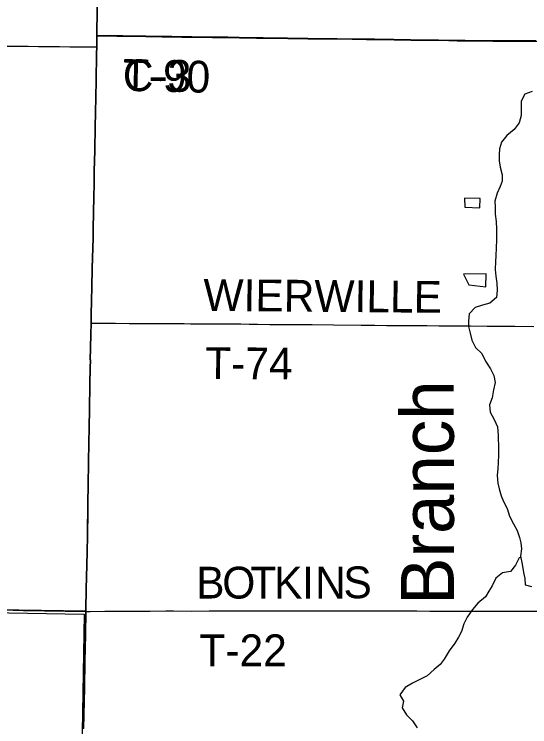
# Model space of a CAD drawing. Extents: x -11.1 to 34, y -3.9 to 22.
# Drawn here: x 7.271 to 8.192, y 18.032 to 19.305 of the extents above; entities that cross this region are included whole.
import ezdxf

# ---------------------------------------------------------------- set-up
doc = ezdxf.new("R2010")
doc.units = 0
for name, color, linetype in [('GM_X_Corporation', 7, 'Continuous'), ('GM_X_County_Road', 7, 'Continuous'), ('GM_X_County_Road_Text', 7, 'Continuous'), ('GM_X_Minor_Lake', 7, 'Continuous'), ('GM_X_Minor_River', 7, 'Continuous'), ('GM_X_Minor_River_Text', 7, 'Continuous'), ('GM_X_Township_Road', 7, 'Continuous'), ('GM_X_Township_Road_Text', 7, 'Continuous')]:
    doc.layers.add(name, color=color, linetype=linetype)

msp = doc.modelspace()

# ---------------------------------------------------------------- linework, layer by layer
at = {"layer": 'GM_X_Corporation'}
for points in [[(6.5234, 18.2515), (7.399, 18.2383), (7.399, 18.2404), (7.3996, 18.2783), (7.4004, 18.3205), (7.4009, 18.3448), (7.4015, 18.3721), (7.4021, 18.4162), (7.4025, 18.4348), (7.403, 18.4609), (7.4037, 18.5063), (7.4048, 18.5684), (7.4054, 18.5976), (7.4062, 18.6448), (7.4067, 18.6728), (7.4068, 18.6865), (7.4065, 18.6884), (7.4065, 18.6901), (7.4065, 18.695), (7.407, 18.7007), (7.4072, 18.7099), (7.4077, 18.7323), (7.4081, 18.7533), (7.4084, 18.7677), (7.4091, 18.7932), (7.4095, 18.8174), (7.4103, 18.851), (7.4116, 18.9056), (7.4119, 18.928), (7.4122, 18.9442), (7.4125, 18.9572), (7.4129, 18.9721), (7.4134, 19.0081), (7.4137, 19.0243), (7.4147, 19.0616), (7.4154, 19.1044), (7.4159, 19.1287), (7.4172, 19.1858), (7.418, 19.2337), (7.4182, 19.2471), (7.4185, 19.2665), (7.4229, 19.6584)], [(7.4229, 19.6584), (7.4185, 19.2665), (7.443, 19.2667), (7.4647, 19.2663), (7.5058, 19.2659), (7.5349, 19.2653), (7.5523, 19.2651), (7.5884, 19.2644), (7.625, 19.2641), (7.6524, 19.2639), (7.6729, 19.2635), (7.7158, 19.2629), (7.7593, 19.2623), (7.7953, 19.2619), (7.8481, 19.2613), (7.9146, 19.2604), (7.9494, 19.2599), (7.9792, 19.2594), (8.0289, 19.2587), (8.0768, 19.2579), (8.1153, 19.2577), (8.1258, 19.2576), (8.1476, 19.2574), (8.1693, 19.2576), (8.2029, 19.2576)], [(8.2029, 19.2576), (8.1693, 19.2576), (8.1476, 19.2574), (8.1258, 19.2576), (8.1153, 19.2577), (8.0768, 19.2579), (8.0289, 19.2587), (7.9792, 19.2594), (7.9494, 19.2599), (7.9146, 19.2604), (7.8481, 19.2613), (7.7953, 19.2619), (7.7593, 19.2623), (7.7158, 19.2629), (7.6729, 19.2635), (7.6524, 19.2639), (7.625, 19.2641), (7.5884, 19.2644), (7.5523, 19.2651), (7.5349, 19.2653), (7.5058, 19.2659), (7.4647, 19.2663), (7.443, 19.2667), (7.4185, 19.2665), (7.4182, 19.2471), (7.418, 19.2337), (7.4172, 19.1858), (7.4159, 19.1287), (7.4154, 19.1044), (7.4147, 19.0616), (7.4137, 19.0243), (7.4134, 19.0081), (7.4129, 18.9721), (7.4125, 18.9572), (7.4122, 18.9442), (7.4119, 18.928), (7.4116, 18.9056), (7.4103, 18.851), (7.4095, 18.8174), (7.4091, 18.7932), (7.4084, 18.7677), (7.4081, 18.7533), (7.4077, 18.7323), (7.4072, 18.7099), (7.407, 18.7007), (7.4065, 18.695), (7.4065, 18.6901), (7.4065, 18.6884), (7.4068, 18.6865), (7.4067, 18.6728), (7.4062, 18.6448), (7.4054, 18.5976), (7.4048, 18.5684), (7.4037, 18.5063), (7.403, 18.4609), (7.4025, 18.4348), (7.4021, 18.4162), (7.4015, 18.3721), (7.4009, 18.3448), (7.4004, 18.3205), (7.3996, 18.2783), (7.399, 18.2404), (7.399, 18.2383), (7.398, 18.1956), (7.3971, 18.149), (7.3961, 18.1012), (7.3946, 18.0285)], [(7.3946, 18.0285), (7.3961, 18.1012), (7.3971, 18.149), (7.398, 18.1956), (7.399, 18.2383), (7.399, 18.2404), (7.3996, 18.2783), (7.4004, 18.3205), (7.4009, 18.3448), (7.4015, 18.3721), (7.4021, 18.4162), (7.4025, 18.4348), (7.403, 18.4609), (7.4037, 18.5063), (7.4048, 18.5684), (7.4054, 18.5976), (7.4062, 18.6448), (7.4067, 18.6728), (7.4068, 18.6865), (7.4065, 18.6884), (7.4065, 18.6901), (7.4065, 18.695), (7.407, 18.7007), (7.4072, 18.7099), (7.4077, 18.7323), (7.4081, 18.7533), (7.4084, 18.7677), (7.4091, 18.7932), (7.4095, 18.8174), (7.4103, 18.851), (7.4116, 18.9056), (7.4119, 18.928), (7.4122, 18.9442), (7.4125, 18.9572), (7.4129, 18.9721), (7.4134, 19.0081), (7.4137, 19.0243), (7.4147, 19.0616), (7.4154, 19.1044), (7.4159, 19.1287), (7.4172, 19.1858), (7.418, 19.2337), (7.4182, 19.2471), (7.4185, 19.2665), (7.443, 19.2667), (7.4647, 19.2663), (7.5058, 19.2659), (7.5349, 19.2653), (7.5523, 19.2651), (7.5884, 19.2644), (7.625, 19.2641), (7.6524, 19.2639), (7.6729, 19.2635), (7.7158, 19.2629), (7.7593, 19.2623), (7.7953, 19.2619), (7.8481, 19.2613), (7.9146, 19.2604), (7.9494, 19.2599), (7.9792, 19.2594), (8.0289, 19.2587), (8.0768, 19.2579), (8.1153, 19.2577), (8.1258, 19.2576), (8.1476, 19.2574), (8.1693, 19.2576), (8.2029, 19.2576)], [(8.2029, 19.2576), (8.1693, 19.2576), (8.1476, 19.2574), (8.1258, 19.2576), (8.1153, 19.2577), (8.0768, 19.2579), (8.0289, 19.2587), (7.9792, 19.2594), (7.9494, 19.2599), (7.9146, 19.2604), (7.8481, 19.2613), (7.7953, 19.2619), (7.7593, 19.2623), (7.7158, 19.2629), (7.6729, 19.2635), (7.6524, 19.2639), (7.625, 19.2641), (7.5884, 19.2644), (7.5523, 19.2651), (7.5349, 19.2653), (7.5058, 19.2659), (7.4647, 19.2663), (7.443, 19.2667), (7.4185, 19.2665), (7.4182, 19.2471), (7.418, 19.2337), (7.4172, 19.1858), (7.4159, 19.1287), (7.4154, 19.1044), (7.4147, 19.0616), (7.4137, 19.0243), (7.4134, 19.0081), (7.4129, 18.9721), (7.4125, 18.9572), (7.4122, 18.9442), (7.4119, 18.928), (7.4116, 18.9056), (7.4103, 18.851), (7.4095, 18.8174), (7.4091, 18.7932), (7.4084, 18.7677), (7.4081, 18.7533), (7.4077, 18.7323), (7.4072, 18.7099), (7.407, 18.7007), (7.4065, 18.695), (7.4065, 18.6901), (7.4065, 18.6884), (7.4068, 18.6865), (7.4067, 18.6728), (7.4062, 18.6448), (7.4054, 18.5976), (7.4048, 18.5684), (7.4037, 18.5063), (7.403, 18.4609), (7.4025, 18.4348), (7.4021, 18.4162), (7.4015, 18.3721), (7.4009, 18.3448), (7.4004, 18.3205), (7.3996, 18.2783), (7.399, 18.2404), (7.399, 18.2383), (7.398, 18.1956), (7.3971, 18.149), (7.3961, 18.1012), (7.3946, 18.0285)], [(7.3946, 18.0285), (7.3961, 18.1012), (7.3971, 18.149), (7.398, 18.1956), (7.399, 18.2383), (6.5234, 18.2515)]]:
    msp.add_lwpolyline(points, dxfattribs=at)
msp.add_lwpolyline([(6.3851, 18.2506), (7.3955, 18.2326), (7.3797, 17.2828), (7.3791, 17.2313), (6.3727, 17.2765), (6.3791, 18.2511)], close=True, dxfattribs=at)
at = {"layer": 'GM_X_County_Road'}
for p, q in [((7.9794, 19.2589), (7.9975, 19.2586)), ((7.4084, 18.7527), (7.4086, 18.7672))]:
    msp.add_line(p, q, dxfattribs=at)
for points in [[(7.4184, 19.2465), (7.4186, 19.2563), (7.4188, 19.266)], [(7.4188, 19.266), (7.4432, 19.2662), (7.4541, 19.266), (7.465, 19.2658), (7.4948, 19.2655), (7.506, 19.2653), (7.5206, 19.2651), (7.5352, 19.2648), (7.5526, 19.2645), (7.5706, 19.2642), (7.5886, 19.2638), (7.6253, 19.2635), (7.6389, 19.2634), (7.6526, 19.2633), (7.6731, 19.263), (7.6918, 19.2627), (7.7039, 19.2625), (7.716, 19.2623), (7.7346, 19.2621), (7.7471, 19.262), (7.7595, 19.2618), (7.7775, 19.2616), (7.7955, 19.2613), (7.8142, 19.2611), (7.8312, 19.261), (7.8483, 19.2608), (7.9002, 19.2601), (7.9322, 19.2596), (7.9496, 19.2594), (7.9794, 19.2589)], [(7.9975, 19.2586), (8.0478, 19.2578), (8.0624, 19.2576), (8.077, 19.2573), (8.0956, 19.2572), (8.1056, 19.2572), (8.1261, 19.257), (8.1369, 19.2569), (8.1478, 19.2569), (8.1695, 19.257), (8.2497, 19.2568)], [(7.4086, 18.7672), (7.409, 18.7799), (7.4093, 18.7926), (7.4095, 18.8048), (7.4098, 18.8169), (7.4106, 18.8504), (7.411, 18.8691), (7.4118, 18.9051), (7.412, 18.9163), (7.4122, 18.9275), (7.4125, 18.9436), (7.4128, 18.9567), (7.4131, 18.9716), (7.4134, 18.9896), (7.4136, 19.0076), (7.4139, 19.0237), (7.4144, 19.0424), (7.4147, 19.0517), (7.4149, 19.061), (7.4157, 19.1039), (7.4161, 19.1281), (7.4165, 19.1468), (7.417, 19.1654), (7.4174, 19.1853), (7.4177, 19.2039), (7.418, 19.2185), (7.4182, 19.2331), (7.4184, 19.2465)], [(7.3992, 18.2378), (7.3996, 18.2585), (7.3997, 18.2681), (7.3999, 18.2777), (7.4002, 18.2964), (7.4006, 18.32), (7.4011, 18.3442), (7.4017, 18.3716), (7.402, 18.3902), (7.4023, 18.4157), (7.4027, 18.4343), (7.4033, 18.4604), (7.4036, 18.479), (7.404, 18.5057), (7.4046, 18.543), (7.4048, 18.5555), (7.4051, 18.5679), (7.4056, 18.5971), (7.406, 18.6157), (7.4062, 18.63), (7.4065, 18.6443), (7.407, 18.6723), (7.4071, 18.686), (7.4067, 18.6879), (7.4072, 18.7001), (7.4074, 18.7094), (7.4077, 18.7206), (7.408, 18.7317), (7.4082, 18.7422), (7.4084, 18.7527)], [(7.3948, 18.028), (7.396, 18.0829), (7.3964, 18.1007), (7.3968, 18.1193), (7.3974, 18.1485), (7.398, 18.1811), (7.3982, 18.1951), (7.3987, 18.2137), (7.3992, 18.2378)]]:
    msp.add_lwpolyline(points, dxfattribs=at)
at = {"layer": 'GM_X_Minor_Lake'}
for points in [[(8.1032, 18.9759), (8.0754, 18.9764), (8.0761, 18.9604)], [(8.0761, 18.9604), (8.1029, 18.9592), (8.1033, 18.9759), (8.1032, 18.9759)], [(8.1136, 18.8177), (8.1141, 18.8411), (8.0736, 18.8406)], [(8.0736, 18.8406), (8.0832, 18.8211), (8.1136, 18.8177)]]:
    msp.add_lwpolyline(points, dxfattribs=at)
at = {"layer": 'GM_X_Minor_River'}
for points in [[(8.1965, 19.1669), (8.1835, 19.1622), (8.1767, 19.1494), (8.1765, 19.1376), (8.1767, 19.1243), (8.173, 19.1107), (8.1643, 19.0987), (8.1512, 19.0883), (8.1414, 19.0763), (8.1381, 19.0642), (8.1372, 19.0543), (8.1377, 19.0429), (8.139, 19.0315), (8.143, 19.0181), (8.1431, 19.0067), (8.1395, 18.9969), (8.134, 18.9852), (8.1295, 18.9708), (8.1301, 18.9606), (8.1306, 18.9476), (8.1319, 18.9347), (8.1324, 18.921), (8.1326, 18.9111), (8.1328, 18.9016), (8.1321, 18.8875), (8.1315, 18.8731), (8.1309, 18.8632), (8.1306, 18.8488), (8.1315, 18.8366), (8.1332, 18.8244), (8.1341, 18.8118), (8.1324, 18.7985), (8.1207, 18.7885), (8.1077, 18.7853), (8.0946, 18.7806), (8.0841, 18.7694), (8.0827, 18.7565), (8.0829, 18.747), (8.0854, 18.7348), (8.0889, 18.7222), (8.0952, 18.7091), (8.1064, 18.6987), (8.113, 18.6852), (8.1219, 18.671), (8.1278, 18.6595), (8.1306, 18.6469), (8.1273, 18.6336), (8.1248, 18.6192), (8.12, 18.6068), (8.1216, 18.5938), (8.1286, 18.5807), (8.1345, 18.5673), (8.1357, 18.5521), (8.1361, 18.5285), (8.1362, 18.5182), (8.1356, 18.5027), (8.135, 18.4932), (8.134, 18.4803), (8.1349, 18.4666), (8.1374, 18.457), (8.141, 18.444), (8.1453, 18.434), (8.152, 18.4214), (8.1559, 18.408), (8.1629, 18.3945), (8.1699, 18.3822), (8.1739, 18.37), (8.176, 18.3601), (8.1774, 18.3498), (8.1756, 18.3365), (8.1784, 18.322), (8.1808, 18.3075), (8.1832, 18.2968), (8.1842, 18.285), (8.1952, 18.2825)], [(8.176, 18.334), (8.1732, 18.3335), (8.1669, 18.3203), (8.1575, 18.3091), (8.1437, 18.3067), (8.1317, 18.2974), (8.125, 18.2835), (8.1191, 18.2737), (8.1128, 18.2639), (8.0996, 18.2524), (8.0898, 18.2411), (8.08, 18.2273), (8.0741, 18.2152), (8.07, 18.202), (8.0649, 18.1918), (8.0585, 18.1809), (8.048, 18.1674), (8.0393, 18.1524), (8.0323, 18.1426), (8.0214, 18.1341), (8.009, 18.1225), (7.9955, 18.1159), (7.9824, 18.1093), (7.9693, 18.102), (7.9599, 18.0888), (7.9665, 18.0773), (7.964, 18.0652), (7.9718, 18.0529), (7.9827, 18.042), (7.9908, 18.0297)]]:
    msp.add_lwpolyline(points, dxfattribs=at)
at = {"layer": 'GM_X_Township_Road'}
for p, q in [((7.9794, 19.2589), (7.9975, 19.2586)), ((7.4084, 18.7527), (7.4086, 18.7672))]:
    msp.add_line(p, q, dxfattribs=at)
for points in [[(7.4188, 19.266), (7.4191, 19.2846), (7.4194, 19.3033), (7.4197, 19.3219)], [(7.4184, 19.2465), (7.4186, 19.2563), (7.4188, 19.266)], [(7.4188, 19.266), (7.4432, 19.2662), (7.4541, 19.266), (7.465, 19.2658), (7.4948, 19.2655), (7.506, 19.2653), (7.5206, 19.2651), (7.5352, 19.2648), (7.5526, 19.2645), (7.5706, 19.2642), (7.5886, 19.2638), (7.6253, 19.2635), (7.6389, 19.2634), (7.6526, 19.2633), (7.6731, 19.263), (7.6918, 19.2627), (7.7039, 19.2625), (7.716, 19.2623), (7.7346, 19.2621), (7.7471, 19.262), (7.7595, 19.2618), (7.7775, 19.2616), (7.7955, 19.2613), (7.8142, 19.2611), (7.8312, 19.261), (7.8483, 19.2608), (7.9002, 19.2601), (7.9322, 19.2596), (7.9496, 19.2594), (7.9794, 19.2589)], [(7.9975, 19.2586), (8.0478, 19.2578), (8.0624, 19.2576), (8.077, 19.2573), (8.0956, 19.2572), (8.1056, 19.2572), (8.1261, 19.257), (8.1369, 19.2569), (8.1478, 19.2569), (8.1695, 19.257), (8.2497, 19.2568)], [(7.1297, 19.2494), (7.1475, 19.2492), (7.1652, 19.249), (7.1839, 19.2488), (7.2025, 19.2486), (7.2211, 19.2484), (7.2398, 19.2482), (7.2584, 19.2481), (7.2771, 19.2479), (7.2957, 19.2477), (7.3143, 19.2475), (7.333, 19.2473), (7.3516, 19.2472), (7.3703, 19.247), (7.3889, 19.2468), (7.4037, 19.2467), (7.4184, 19.2465)], [(7.4086, 18.7672), (7.409, 18.7799), (7.4093, 18.7926), (7.4095, 18.8048), (7.4098, 18.8169), (7.4106, 18.8504), (7.411, 18.8691), (7.4118, 18.9051), (7.412, 18.9163), (7.4122, 18.9275), (7.4125, 18.9436), (7.4128, 18.9567), (7.4131, 18.9716), (7.4134, 18.9896), (7.4136, 19.0076), (7.4139, 19.0237), (7.4144, 19.0424), (7.4147, 19.0517), (7.4149, 19.061), (7.4157, 19.1039), (7.4161, 19.1281), (7.4165, 19.1468), (7.417, 19.1654), (7.4174, 19.1853), (7.4177, 19.2039), (7.418, 19.2185), (7.4182, 19.2331), (7.4184, 19.2465)], [(7.3992, 18.2378), (7.3996, 18.2585), (7.3997, 18.2681), (7.3999, 18.2777), (7.4002, 18.2964), (7.4006, 18.32), (7.4011, 18.3442), (7.4017, 18.3716), (7.402, 18.3902), (7.4023, 18.4157), (7.4027, 18.4343), (7.4033, 18.4604), (7.4036, 18.479), (7.404, 18.5057), (7.4046, 18.543), (7.4048, 18.5555), (7.4051, 18.5679), (7.4056, 18.5971), (7.406, 18.6157), (7.4062, 18.63), (7.4065, 18.6443), (7.407, 18.6723), (7.4071, 18.686), (7.4067, 18.6879), (7.4072, 18.7001), (7.4074, 18.7094), (7.4077, 18.7206), (7.408, 18.7317), (7.4082, 18.7422), (7.4084, 18.7527)], [(7.4084, 18.7527), (7.4157, 18.7527), (7.4169, 18.7527), (7.4275, 18.7526), (7.4387, 18.7527), (7.4517, 18.7527), (7.476, 18.7523), (7.5089, 18.7524), (7.5257, 18.7524), (7.5325, 18.7524), (7.5443, 18.7524), (7.5549, 18.7523), (7.5747, 18.752), (7.5859, 18.7519), (7.6039, 18.7517), (7.6331, 18.7517), (7.6487, 18.7517), (7.6611, 18.7516), (7.676, 18.7514), (7.6909, 18.7513), (7.7058, 18.751), (7.7275, 18.7507), (7.7406, 18.7506), (7.753, 18.7505), (7.7841, 18.7502), (7.8033, 18.7502), (7.8412, 18.7497), (7.8909, 18.7494), (7.9151, 18.749), (7.9363, 18.7488), (7.9562, 18.7487), (7.9767, 18.7487), (8.0044, 18.7486)], [(8.0044, 18.7486), (8.0083, 18.7486), (8.0294, 18.7482), (8.0387, 18.7481), (8.0673, 18.748), (8.086, 18.7479), (8.1158, 18.7476), (8.1313, 18.7476), (8.1655, 18.7475), (8.1996, 18.7471)], [(7.2688, 18.2399), (7.2874, 18.2396), (7.3061, 18.2393), (7.3247, 18.239), (7.3433, 18.2387), (7.362, 18.2384), (7.3806, 18.2381), (7.3992, 18.2378)], [(7.3948, 18.028), (7.396, 18.0829), (7.3964, 18.1007), (7.3968, 18.1193), (7.3974, 18.1485), (7.398, 18.1811), (7.3982, 18.1951), (7.3987, 18.2137), (7.3992, 18.2378)], [(7.3992, 18.2378), (7.4063, 18.2378), (7.4325, 18.238), (7.4679, 18.2382), (7.5139, 18.2382), (7.5418, 18.2386), (7.5555, 18.2387), (7.5884, 18.2384), (7.6189, 18.2386), (7.6406, 18.2386), (7.6885, 18.2386), (7.7195, 18.2385), (7.8121, 18.2386), (7.8457, 18.2385), (7.8699, 18.2387), (7.8867, 18.2388), (7.9215, 18.2388), (7.9482, 18.2389), (7.97, 18.2387), (7.9905, 18.2386), (8.0135, 18.2384), (8.0333, 18.2384), (8.0669, 18.2382), (8.0812, 18.2381), (8.0949, 18.2381), (8.111, 18.2383), (8.1259, 18.2382), (8.1446, 18.2382), (8.1905, 18.2383), (8.216, 18.2381)]]:
    msp.add_lwpolyline(points, dxfattribs=at)

# ---------------------------------------------------------------- texts
at = {"layer": 'GM_X_County_Road_Text'}
msp.add_text('C-3', height=0.05682, rotation=359.0877, dxfattribs=at).set_placement((7.4644, 19.168))
at = {"layer": 'GM_X_Minor_River_Text'}
msp.add_text('Branch', height=0.09468, rotation=90.0353, dxfattribs=at).set_placement((8.0566, 18.2495))
at = {"layer": 'GM_X_Township_Road_Text'}
for s, height, rotation, p in [('T-90', 0.05682, 358.5868, (7.4642, 19.1683)), ('WIERWILLE', 0.05682, 359.5167, (7.6087, 18.7749)), ('T-74', 0.05682, 359.6509, (7.6119, 18.6531)), ('B', 0.0568, 0, (7.5959, 18.2607)), ('O', 0.0568, 0, (7.6426, 18.2607)), ('T', 0.0568, 0, (7.6926, 18.2607)), ('K', 0.0568, 0, (7.7351, 18.2607)), ('I', 0.0568, 0, (7.7851, 18.2607)), ('N', 0.0568, 0.0338, (7.8084, 18.2607)), ('S', 0.0568, 0.9998, (7.8595, 18.2608)), ('T-22', 0.05682, 0, (7.6017, 18.1398))]:
    msp.add_text(s, height=height, rotation=rotation, dxfattribs=at).set_placement(p)

doc.saveas('drawing.dxf')
